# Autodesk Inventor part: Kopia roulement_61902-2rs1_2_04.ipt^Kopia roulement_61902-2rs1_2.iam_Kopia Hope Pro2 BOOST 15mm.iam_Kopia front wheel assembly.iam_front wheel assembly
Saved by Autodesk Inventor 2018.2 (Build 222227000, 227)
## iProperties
Created: 2017-09
Part Number: Kopia roulement_61902-2rs1_2_04.ipt^Kopia roulement_61902-2rs1_2.iam_Kopia Hope Pro2 BOOST 15mm.iam_Kopia front wheel assembly.iam_front wheel assembly
Material: Ogólny
Document SubType Name: Modeling
Designer: Tomasz
Density: 1 g/cm^3
Appearance: Domyślna
Author: Tomasz
Sending System: SolidWorks 2017
Last Author: Tomasz
Last Saved: 2017-09-11
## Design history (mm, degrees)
